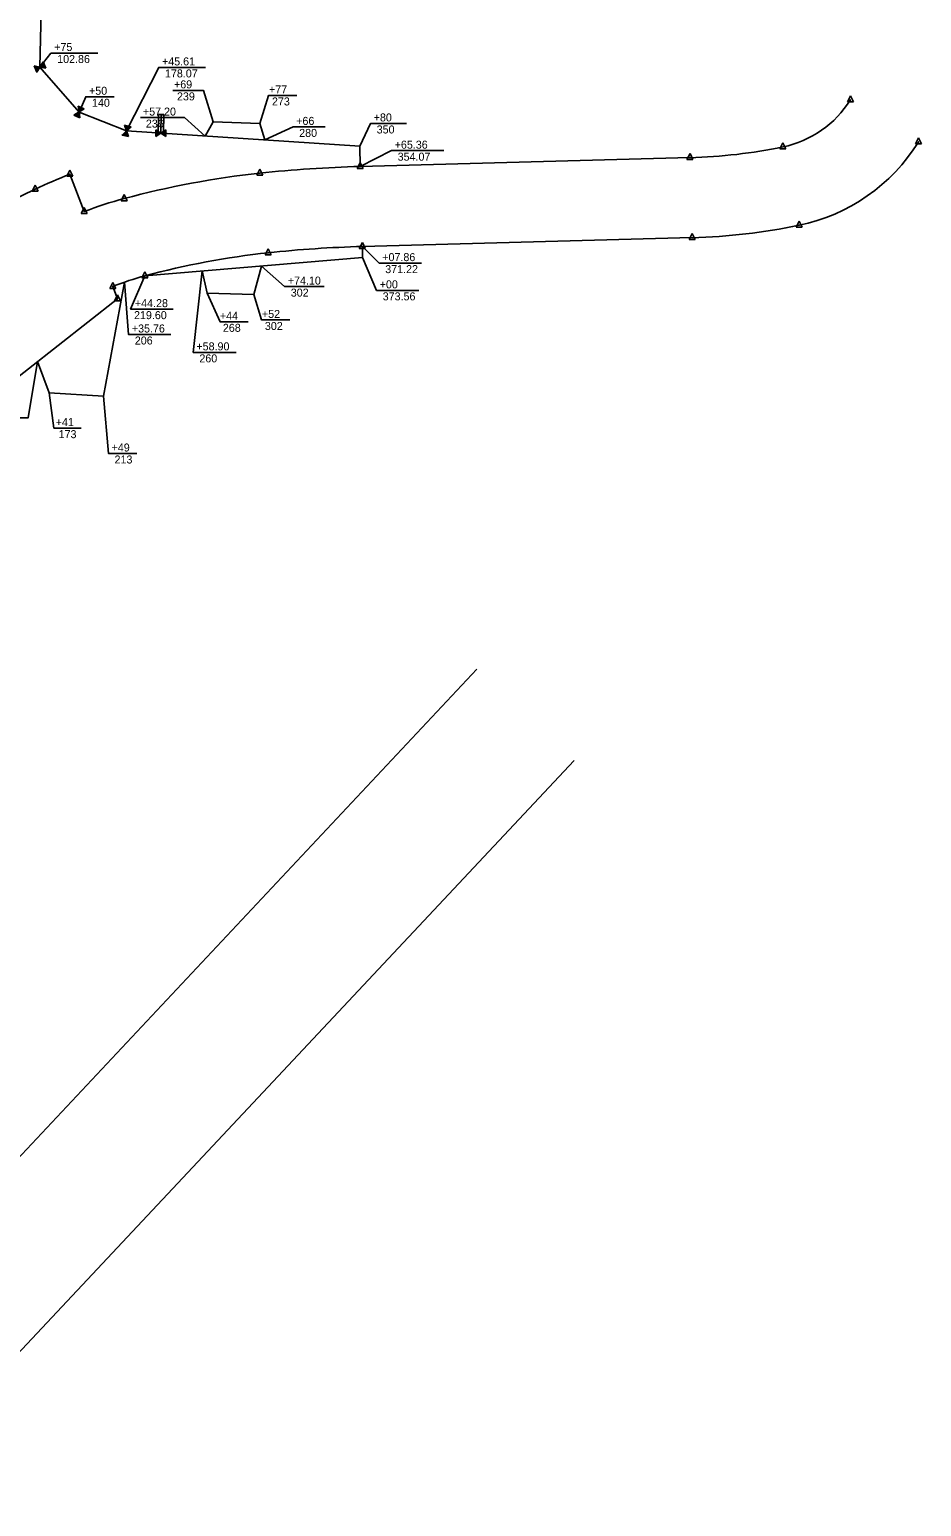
# Model space of a CAD drawing. Extents: x 979729 to 993523, y 1834148 to 1845433.
# Drawn here: x 992855 to 993523, y 1839683 to 1840790 of the extents above; entities that cross this region are included whole.
import ezdxf

# ---------------------------------------------------------------- set-up
doc = ezdxf.new("R2010")
doc.units = 0
for name, color, linetype in [('42', 7, 'Continuous'), ('51', 7, 'Continuous'), ('53', 7, 'Continuous'), ('R_Draft', 7, 'Continuous'), ('S_EXIST_ROW', 7, 'Continuous')]:
    doc.layers.add(name, color=color, linetype=linetype)

msp = doc.modelspace()

# ---------------------------------------------------------------- linework, layer by layer
at = {"layer": '42'}
for p, q in [((992862.7, 1840762.3), (992858.3, 1840763.1)), ((992862.6, 1840762.2), (992858.3, 1840763)), ((992862.4, 1840762), (992858.4, 1840762.7)), ((992862.3, 1840761.8), (992858.5, 1840762.4)), ((992862.2, 1840761.6), (992858.7, 1840762.2)), ((992862.1, 1840761.3), (992858.8, 1840761.9)), ((992861.9, 1840761.1), (992858.9, 1840761.6)), ((992861.8, 1840760.9), (992859, 1840761.3)), ((992861.6, 1840760.6), (992859.2, 1840761.1)), ((992861.4, 1840760.4), (992859.3, 1840760.8)), ((992861.2, 1840759.9), (992859.5, 1840760.2)), ((992861.2, 1840760.2), (992859.6, 1840760.5)), ((992861.1, 1840759.7), (992859.6, 1840760)), ((992860.9, 1840759.5), (992859.8, 1840759.7)), ((992860.7, 1840759.3), (992859.9, 1840759.4)), ((992860.6, 1840759), (992860, 1840759.1)), ((992860.4, 1840758.8), (992860.1, 1840758.9)), ((992860.3, 1840758.6), (992860.2, 1840758.6)), ((992860.3, 1840758.5), (992862.7, 1840762.3)), ((992862.7, 1840762.3), (992865.1, 1840766.1)), ((992867.1, 1840761.5), (992862.7, 1840762.3)), ((992862.8, 1840762.3), (992865.2, 1840766)), ((992863.1, 1840762.3), (992865.3, 1840765.7)), ((992863.3, 1840762.2), (992865.4, 1840765.5)), ((992863.6, 1840762.2), (992865.5, 1840765.2)), ((992863.9, 1840762.1), (992865.6, 1840764.9)), ((992864.2, 1840762.1), (992865.8, 1840764.6)), ((992864.4, 1840762), (992865.9, 1840764.4)), ((992864.7, 1840762), (992866, 1840764.1)), ((992865, 1840762), (992866.1, 1840763.8)), ((992865.2, 1840762), (992866.2, 1840763.4)), ((992865.5, 1840761.8), (992866.4, 1840763.3)), ((992865.7, 1840761.8), (992866.5, 1840763)), ((992866, 1840761.8), (992866.6, 1840762.7)), ((992866.3, 1840761.7), (992866.7, 1840762.4)), ((992866.5, 1840761.7), (992866.9, 1840762.2)), ((992866.8, 1840761.6), (992867, 1840761.9)), ((992867.1, 1840761.6), (992867.1, 1840761.6)), ((992888.2, 1840726.2), (992892, 1840728.6)), ((992888.3, 1840726.3), (992888.3, 1840726.2)), ((992888.5, 1840726.4), (992888.5, 1840726.1)), ((992888.7, 1840726.6), (992888.8, 1840726)), ((992889, 1840726.7), (992889.1, 1840725.8)), ((992889.2, 1840726.8), (992889.4, 1840725.7)), ((992889.4, 1840727), (992889.6, 1840725.6)), ((992889.6, 1840727.1), (992889.9, 1840725.4)), ((992889.9, 1840727.2), (992890.1, 1840725.5)), ((992890.1, 1840727.4), (992890.4, 1840725.2)), ((992890.3, 1840727.5), (992890.7, 1840725.1)), ((992890.6, 1840727.7), (992891, 1840724.9)), ((992890.8, 1840727.8), (992891.3, 1840724.8)), ((992891, 1840728), (992891.5, 1840724.7)), ((992891.3, 1840728.1), (992891.8, 1840724.5)), ((992891.4, 1840733), (992891.4, 1840733)), ((992891.4, 1840733), (992892, 1840728.6)), ((992891.4, 1840732.7), (992891.7, 1840732.9)), ((992891.5, 1840732.4), (992892, 1840732.7)), ((992891.5, 1840732.2), (992892.3, 1840732.6)), ((992891.5, 1840728.2), (992892.1, 1840724.4)), ((992891.6, 1840731.9), (992892.5, 1840732.5)), ((992891.6, 1840731.6), (992892.8, 1840732.4)), ((992891.6, 1840731.4), (992893.1, 1840732.2)), ((992891.7, 1840731.1), (992893.2, 1840732)), ((992891.7, 1840730.8), (992893.6, 1840732)), ((992891.7, 1840728.3), (992892.3, 1840724.3)), ((992891.8, 1840730.6), (992893.9, 1840731.8)), ((992891.8, 1840730.3), (992894.2, 1840731.7)), ((992891.9, 1840730), (992894.4, 1840731.6)), ((992891.9, 1840729.8), (992894.7, 1840731.5)), ((992891.9, 1840729.5), (992895, 1840731.3)), ((992892, 1840729.2), (992895.3, 1840731.2)), ((992892, 1840729), (992895.5, 1840731.1)), ((992892, 1840728.7), (992895.8, 1840731)), ((992892, 1840728.6), (992895.9, 1840730.9)), ((992892, 1840728.6), (992892.7, 1840724.1)), ((992892, 1840728.5), (992892.6, 1840724.2)), ((992951.3, 1840712.7), (992951.5, 1840726.7)), ((992951.5, 1840726.7), (992955.5, 1840726.7)), ((992953.3, 1840712.7), (992953.5, 1840726.7)), ((992955.3, 1840712.7), (992955.5, 1840726.7)), ((992924.3, 1840711.3), (992927.7, 1840714.4)), ((992924.4, 1840711.4), (992924.4, 1840711.3)), ((992924.6, 1840711.6), (992924.7, 1840711.3)), ((992924.8, 1840711.8), (992925, 1840711.2)), ((992925, 1840711.9), (992925.3, 1840711.1)), ((992925.2, 1840712.1), (992925.6, 1840711)), ((992925.4, 1840712.3), (992925.9, 1840711)), ((992925.6, 1840712.5), (992926.2, 1840710.9)), ((992925.8, 1840712.6), (992926.4, 1840711)), ((992926, 1840712.8), (992926.8, 1840710.7)), ((992926.1, 1840718.6), (992927.7, 1840714.4)), ((992926.2, 1840718.6), (992926.2, 1840718.6)), ((992926.2, 1840713), (992927, 1840710.7)), ((992926.3, 1840718.3), (992926.5, 1840718.5)), ((992926.4, 1840718.1), (992926.8, 1840718.5)), ((992926.4, 1840713.2), (992927.3, 1840710.6)), ((992926.5, 1840717.8), (992927.1, 1840718.4)), ((992926.5, 1840717.5), (992927.4, 1840718.3)), ((992926.6, 1840717.3), (992927.7, 1840718.2)), ((992926.6, 1840713.4), (992927.6, 1840710.5)), ((992926.7, 1840717), (992928, 1840718.2)), ((992926.8, 1840713.6), (992927.9, 1840710.5)), ((992926.9, 1840716.8), (992928.1, 1840718)), ((992926.9, 1840716.5), (992928.6, 1840718)), ((992927, 1840716.3), (992928.9, 1840718)), ((992927, 1840713.7), (992928.2, 1840710.4)), ((992927.1, 1840716), (992929.1, 1840717.9)), ((992927.2, 1840715.8), (992929.4, 1840717.8)), ((992927.2, 1840713.9), (992928.5, 1840710.3)), ((992927.3, 1840715.5), (992929.7, 1840717.7)), ((992927.4, 1840715.3), (992930, 1840717.7)), ((992927.4, 1840714.1), (992928.8, 1840710.2)), ((992927.5, 1840715), (992930.3, 1840717.6)), ((992927.6, 1840714.8), (992930.6, 1840717.5)), ((992927.6, 1840714.5), (992930.9, 1840717.4)), ((992927.6, 1840714.3), (992929.1, 1840710.2)), ((992927.7, 1840714.4), (992931, 1840717.4)), ((992927.7, 1840714.4), (992929.2, 1840710.1)), ((992953.3, 1840712.7), (992949.6, 1840715.2)), ((992953.2, 1840712.7), (992949.6, 1840715.1)), ((992953, 1840712.5), (992949.6, 1840714.8)), ((992952.8, 1840712.4), (992949.6, 1840714.5)), ((992952.5, 1840712.2), (992949.6, 1840714.2)), ((992952.3, 1840712.1), (992949.6, 1840713.9)), ((992952.1, 1840712), (992949.6, 1840713.6)), ((992951.9, 1840711.8), (992949.6, 1840713.3)), ((992951.6, 1840711.7), (992949.6, 1840713)), ((992951.4, 1840711.5), (992949.6, 1840712.7)), ((992949.6, 1840710.2), (992953.3, 1840712.7)), ((992951, 1840711.2), (992949.6, 1840712.1)), ((992950.8, 1840711), (992949.6, 1840711.8)), ((992950.5, 1840710.9), (992949.6, 1840711.5)), ((992950.3, 1840710.8), (992949.6, 1840711.2)), ((992951.1, 1840711.4), (992949.7, 1840712.3)), ((992951.3, 1840712.7), (992955.3, 1840712.7)), ((992953.3, 1840712.7), (992957.1, 1840715.2)), ((992957.1, 1840710.2), (992953.3, 1840712.7)), ((992953.4, 1840712.7), (992957.1, 1840715.1)), ((992953.7, 1840712.5), (992957.1, 1840714.8)), ((992953.9, 1840712.4), (992957.1, 1840714.5)), ((992954.1, 1840712.2), (992957.1, 1840714.2)), ((992954.3, 1840712.1), (992957.1, 1840713.9)), ((992954.6, 1840711.9), (992957.1, 1840713.6)), ((992954.8, 1840711.8), (992957.1, 1840713.3)), ((992955, 1840711.6), (992957.1, 1840713)), ((992955.2, 1840711.5), (992957.1, 1840712.7)), ((992955.5, 1840711.3), (992956.9, 1840712.3)), ((992955.7, 1840711.1), (992957.1, 1840712.1)), ((992955.9, 1840711), (992957.1, 1840711.8)), ((992956.1, 1840710.8), (992957.1, 1840711.5)), ((992956.3, 1840710.7), (992957.1, 1840711.2)), ((992950.1, 1840710.6), (992949.6, 1840710.9)), ((992949.8, 1840710.5), (992949.6, 1840710.6)), ((992949.6, 1840710.3), (992949.6, 1840710.3)), ((992956.6, 1840710.5), (992957.1, 1840710.9)), ((992956.8, 1840710.4), (992957.1, 1840710.6)), ((992957, 1840710.2), (992957.1, 1840710.3))]:
    msp.add_line(p, q, dxfattribs=at)
for points in [[(992860.3, 1840758.5), (992858.3, 1840763.1)], [(992867.1, 1840761.5), (992865.1, 1840766.1)], [(992888.2, 1840726.2), (992892.7, 1840724.1)], [(992891.4, 1840733), (992895.9, 1840730.9)], [(992924.3, 1840711.3), (992929.2, 1840710.1)], [(992926.1, 1840718.6), (992931, 1840717.4)], [(992949.6, 1840710.2), (992949.6, 1840715.2)], [(992957.1, 1840710.2), (992957.1, 1840715.2)]]:
    msp.add_lwpolyline(points, dxfattribs=at)
at = {"layer": '51'}
for p, q in [((992864.5, 1840840.2), (992862.7, 1840762.3)), ((992862.7, 1840762.3), (992862.7, 1840762.3)), ((992862.7, 1840762.3), (992892, 1840728.5)), ((993104.4, 1840627.7), (993104.6, 1840619.5)), ((993104.6, 1840619.5), (992941.4, 1840605.7))]:
    msp.add_line(p, q, dxfattribs=at)
msp.add_lwpolyline([(992892, 1840728.5), (992927.7, 1840714.4), (993102.6, 1840702.9), (993102.7, 1840687.7)], dxfattribs=at)
at = {"layer": '53'}
for p, q in [((992986.6, 1840710.5), (992992.6, 1840721.1)), ((992992.6, 1840721.1), (993027.5, 1840720)), ((993027.5, 1840720), (993031.4, 1840707.6)), ((993023, 1840591.8), (993028.8, 1840613.1)), ((992910.3, 1840515.5), (992926.1, 1840601.1)), ((992984.2, 1840609.4), (992988.1, 1840592.9)), ((992988.1, 1840592.9), (993023, 1840591.8)), ((992861, 1840541.6), (992869.6, 1840518.1)), ((992869.6, 1840518.1), (992910.3, 1840515.5))]:
    msp.add_line(p, q, dxfattribs=at)
at = {"layer": 'R_Draft'}
for p, q in [((992877, 1840772.8), (992906, 1840772.8)), ((992957.8, 1840762), (992986.8, 1840762)), ((992962.3, 1840744.8), (992979.3, 1840744.8)), ((992903.1, 1840740), (992918.3, 1840740)), ((993040.1, 1840741), (993055.2, 1840741)), ((992938.1, 1840724.4), (992965, 1840724.4)), ((993058.4, 1840717.4), (993076.6, 1840717.4)), ((993116.5, 1840720), (993137.4, 1840720)), ((993132.2, 1840699.6), (993165.5, 1840699.6)), ((993122.9, 1840615.3), (993148.7, 1840615.3)), ((993052.1, 1840597.7), (993075.8, 1840597.7)), ((993121, 1840594.9), (993146.8, 1840594.9)), ((992936.7, 1840580.8), (992962.6, 1840580.8)), ((993003.7, 1840571.3), (993018.8, 1840571.3)), ((993034.8, 1840572.7), (993049.9, 1840572.7)), ((992935, 1840561.8), (992960.8, 1840561.8)), ((992983.6, 1840548.4), (993009.8, 1840548.4)), ((992879.2, 1840491.6), (992893.5, 1840491.6)), ((992920, 1840472.6), (992935.4, 1840472.6))]:
    msp.add_line(p, q, dxfattribs=at)
for points in [[(992862.7, 1840762.3), (992871, 1840772.8), (992877, 1840772.8)], [(992927.7, 1840714.4), (992951.8, 1840762), (992957.8, 1840762)], [(992992.6, 1840721.1), (992985.3, 1840744.8), (992979.3, 1840744.8)], [(992892, 1840728.5), (992897.1, 1840740), (992903.1, 1840740)], [(993027.5, 1840720), (993034.1, 1840741), (993040.1, 1840741)], [(992986.6, 1840710.5), (992971, 1840724.4), (992965, 1840724.4)], [(993031.4, 1840707.6), (993052.4, 1840717.4), (993058.4, 1840717.4)], [(993102.6, 1840702.9), (993110.5, 1840720), (993116.5, 1840720)], [(993102.7, 1840687.7), (993126.2, 1840699.6), (993132.2, 1840699.6)], [(993104.4, 1840627.7), (993116.9, 1840615.3), (993122.9, 1840615.3)], [(993028.8, 1840613.1), (993046.1, 1840597.7), (993052.1, 1840597.7)], [(993104.6, 1840619.5), (993115, 1840594.9), (993121, 1840594.9)], [(992926.1, 1840601.1), (992929, 1840561.8), (992935, 1840561.8)], [(992941.4, 1840605.7), (992930.7, 1840580.8), (992936.7, 1840580.8)], [(992984.2, 1840609.4), (992977.6, 1840548.4), (992983.6, 1840548.4)], [(992988.1, 1840592.9), (992997.7, 1840571.3), (993003.7, 1840571.3)], [(993023, 1840591.8), (993028.8, 1840572.7), (993034.8, 1840572.7)], [(992861, 1840541.6), (992854, 1840499.4), (992848, 1840499.4)], [(992869.6, 1840518.1), (992873.2, 1840491.6), (992879.2, 1840491.6)], [(992910.3, 1840515.5), (992914, 1840472.6), (992920, 1840472.6)]]:
    msp.add_lwpolyline(points, dxfattribs=at)
at = {"layer": 'S_EXIST_ROW'}
for p, q in [((993470.3, 1840740.8), (993468, 1840736.2)), ((993468, 1840736.2), (993472.5, 1840736.2)), ((993470.3, 1840740.8), (993472.5, 1840736.2)), ((993470.3, 1840737.7), (993470.3, 1840737.7)), ((993419.6, 1840705.5), (993417.4, 1840700.9)), ((993417.4, 1840700.9), (993421.9, 1840700.9)), ((993419.6, 1840705.5), (993421.9, 1840700.9)), ((993419.6, 1840702.4), (993419.6, 1840702.4)), ((993521.2, 1840709.1), (993519, 1840704.6)), ((993519, 1840704.6), (993523.5, 1840704.6)), ((993521.2, 1840709.1), (993523.5, 1840704.6)), ((993521.2, 1840706.1), (993521.2, 1840706.1)), ((993102.8, 1840690.7), (993100.5, 1840686.2)), ((993102.7, 1840687.7), (993350, 1840694.4)), ((993102.8, 1840690.7), (993105, 1840686.2)), ((993350, 1840697.4), (993347.7, 1840692.9)), ((993347.7, 1840692.9), (993352.2, 1840692.9)), ((993350, 1840697.4), (993352.2, 1840692.9)), ((993350, 1840694.4), (993350, 1840694.4)), ((992885, 1840684.9), (992882.8, 1840680.4)), ((992882.8, 1840680.4), (992887.3, 1840680.4)), ((992885, 1840684.9), (992887.3, 1840680.4)), ((992885, 1840681.9), (992885, 1840681.9)), ((992885, 1840681.9), (992895.8, 1840653.9)), ((993027.5, 1840685.7), (993025.2, 1840681.2)), ((993025.2, 1840681.2), (993029.7, 1840681.2)), ((993027.5, 1840685.7), (993029.7, 1840681.2)), ((993027.5, 1840682.7), (993027.5, 1840682.7)), ((993100.5, 1840686.2), (993105, 1840686.2)), ((993102.7, 1840687.7), (993102.7, 1840687.7)), ((992827.5, 1840655.3), (992859.2, 1840670.7)), ((992859.2, 1840673.7), (992856.9, 1840669.2)), ((992856.9, 1840669.2), (992861.4, 1840669.2)), ((992859.2, 1840673.7), (992861.4, 1840669.2)), ((992859.2, 1840670.7), (992859.2, 1840670.7)), ((992925.8, 1840666.7), (992923.5, 1840662.1)), ((992925.8, 1840666.7), (992928, 1840662.1)), ((992895.8, 1840656.9), (992893.6, 1840652.4)), ((992895.8, 1840656.9), (992898, 1840652.4)), ((992923.5, 1840662.1), (992928, 1840662.1)), ((992925.8, 1840663.7), (992925.8, 1840663.7)), ((992893.6, 1840652.4), (992898, 1840652.4)), ((992895.8, 1840653.9), (992895.8, 1840653.9)), ((993431.8, 1840646.7), (993429.5, 1840642.2)), ((993431.8, 1840646.7), (993434, 1840642.2)), ((993104.4, 1840627.7), (993351.6, 1840634.4)), ((993351.6, 1840637.4), (993349.4, 1840632.9)), ((993351.6, 1840637.4), (993353.8, 1840632.9)), ((993351.6, 1840634.4), (993351.6, 1840634.4)), ((993429.5, 1840642.2), (993434, 1840642.2)), ((993431.8, 1840643.7), (993431.8, 1840643.7)), ((993033.8, 1840626.1), (993031.6, 1840621.5)), ((993033.8, 1840626.1), (993036.1, 1840621.5)), ((993033.8, 1840623), (993033.8, 1840623)), ((993104.4, 1840630.8), (993102.1, 1840626.2)), ((993102.1, 1840626.2), (993106.6, 1840626.2)), ((993104.4, 1840630.8), (993106.6, 1840626.2)), ((993104.4, 1840627.7), (993104.4, 1840627.7)), ((993349.4, 1840632.9), (993353.8, 1840632.9)), ((993031.6, 1840621.5), (993036.1, 1840621.5)), ((992917.3, 1840600.9), (992915.1, 1840596.4)), ((992917.3, 1840600.9), (992919.6, 1840596.4)), ((992941.4, 1840608.8), (992939.2, 1840604.2)), ((992939.2, 1840604.2), (992943.7, 1840604.2)), ((992941.4, 1840608.8), (992943.7, 1840604.2)), ((992941.4, 1840605.7), (992941.4, 1840605.7)), ((992915.1, 1840596.4), (992919.6, 1840596.4)), ((992917.3, 1840597.9), (992917.3, 1840597.9)), ((992920.9, 1840588.5), (992917.3, 1840597.9)), ((992920.9, 1840591.6), (992918.7, 1840587)), ((992920.9, 1840591.6), (992923.2, 1840587)), ((992831.6, 1840518.6), (992920.9, 1840588.5)), ((992918.7, 1840587), (992923.2, 1840587)), ((992920.9, 1840588.5), (992920.9, 1840588.5)), ((990293.2, 1837222.2), (993190.2, 1840310.9)), ((990366.1, 1837153.8), (993263.1, 1840242.5))]:
    msp.add_line(p, q, dxfattribs=at)
for centre, radius in [((993470.3, 1840737.7), 0.0384), ((993470.3, 1840737.7), 0.0768), ((993419.6, 1840702.4), 0.0384), ((993419.6, 1840702.4), 0.0768), ((993521.2, 1840706.1), 0.0768), ((993521.2, 1840706.1), 0.0384), ((993350, 1840694.4), 0.0384), ((993350, 1840694.4), 0.0768), ((992885, 1840681.9), 0.0768), ((992885, 1840681.9), 0.0384), ((993027.5, 1840682.7), 0.0768), ((993027.5, 1840682.7), 0.0384), ((993102.7, 1840687.7), 0.0768), ((993102.7, 1840687.7), 0.0384), ((992859.2, 1840670.7), 0.0768), ((992859.2, 1840670.7), 0.0384), ((992925.8, 1840663.7), 0.0384), ((992925.8, 1840663.7), 0.0768), ((992895.8, 1840653.9), 0.0768), ((992895.8, 1840653.9), 0.0384), ((993351.6, 1840634.4), 0.0768), ((993351.6, 1840634.4), 0.0384), ((993431.8, 1840643.7), 0.0384), ((993431.8, 1840643.7), 0.0768), ((993033.8, 1840623), 0.0768), ((993033.8, 1840623), 0.0384), ((993104.4, 1840627.7), 0.0384), ((993104.4, 1840627.7), 0.0768), ((992941.4, 1840605.7), 0.0384), ((992941.4, 1840605.7), 0.0768), ((992917.3, 1840597.9), 0.0768), ((992917.3, 1840597.9), 0.0384), ((992920.9, 1840588.5), 0.0768), ((992920.9, 1840588.5), 0.0384)]:
    msp.add_circle(centre, radius, dxfattribs=at)
for centre, radius, start, end in [((993403.8, 1840779), 78.2, 281.6549, 328.1392), ((993339.3, 1841092), 397.8, 271.543, 281.6549), ((993403.8, 1840779), 138.2, 281.6549, 328.1392), ((993005.7, 1840368.1), 336.2, 111.0255, 115.8302), ((993097, 1840030.2), 656.2, 96.08, 105.1227), ((993128.4, 1839735.1), 953, 91.543, 96.08), ((993005.7, 1840368.1), 306.2, 105.1227, 111.0255), ((993339.3, 1841092), 457.8, 271.543, 281.6549), ((993097, 1840030.2), 596.2, 96.08, 105.1227), ((993128.4, 1839735.1), 893, 91.543, 96.08), ((993005.7, 1840368.1), 246.2, 105.1227, 111.0255)]:
    msp.add_arc(centre, radius, start, end, dxfattribs=at)

# ---------------------------------------------------------------- texts
at = {"layer": 'R_Draft'}
for s, rotation, p in [('+75', 360, (992873.4, 1840774.3)), (' 102.86', 360, (992873.4, 1840765.3)), ('+45.61', 360, (992954.2, 1840763.5)), (' 178.07', 360, (992954.2, 1840754.5)), ('+50', 360, (992899.5, 1840741.5)), ('+69', 360, (992963.2, 1840746.3)), ('+77', 360, (993034.4, 1840742.5)), (' 140', 360, (992899.5, 1840732.5)), (' 239', 360, (992963.2, 1840737.3)), (' 273', 360, (993034.4, 1840733.5)), ('+57.20', 360, (992939.9, 1840725.9)), (' 236', 360, (992939.9, 1840716.9)), ('+66', 360, (993054.8, 1840718.9)), ('+80', 360, (993112.9, 1840721.5)), (' 280', 360, (993054.8, 1840709.9)), (' 350', 360, (993112.9, 1840712.5)), ('+65.36', 360, (993128.6, 1840701.1)), (' 354.07', 360, (993128.6, 1840692.1)), ('+07.86', 360, (993119.3, 1840616.8)), (' 371.22', 360, (993119.3, 1840607.8)), ('+74.10', 360, (993048.5, 1840599.2)), ('+00', 360, (993117.4, 1840596.4)), (' 302', 360, (993048.5, 1840590.2)), (' 373.56', 360, (993117.4, 1840587.4)), (' 219.60', 0, (992931, 1840573.3)), ('+44.28', 0, (992933.9, 1840582.3)), ('+44', 360, (992997.6, 1840572.8)), ('+52', 360, (993029.1, 1840574.2)), ('+35.76', 360, (992931.6, 1840563.3)), (' 268', 360, (992997.6, 1840563.8)), (' 302', 360, (993029.1, 1840565.2)), (' 206', 360, (992931.6, 1840554.3)), ('+58.90', 360, (992980, 1840549.9)), (' 260', 360, (992980, 1840540.9)), ('+41', 360, (992874.5, 1840493.1)), (' 173', 360, (992874.5, 1840484.1)), ('+49', 360, (992916.4, 1840474.1)), (' 213', 360, (992916.4, 1840465.1))]:
    msp.add_text(s, height=6, rotation=rotation, dxfattribs=at).set_placement(p)

doc.saveas('drawing.dxf')
